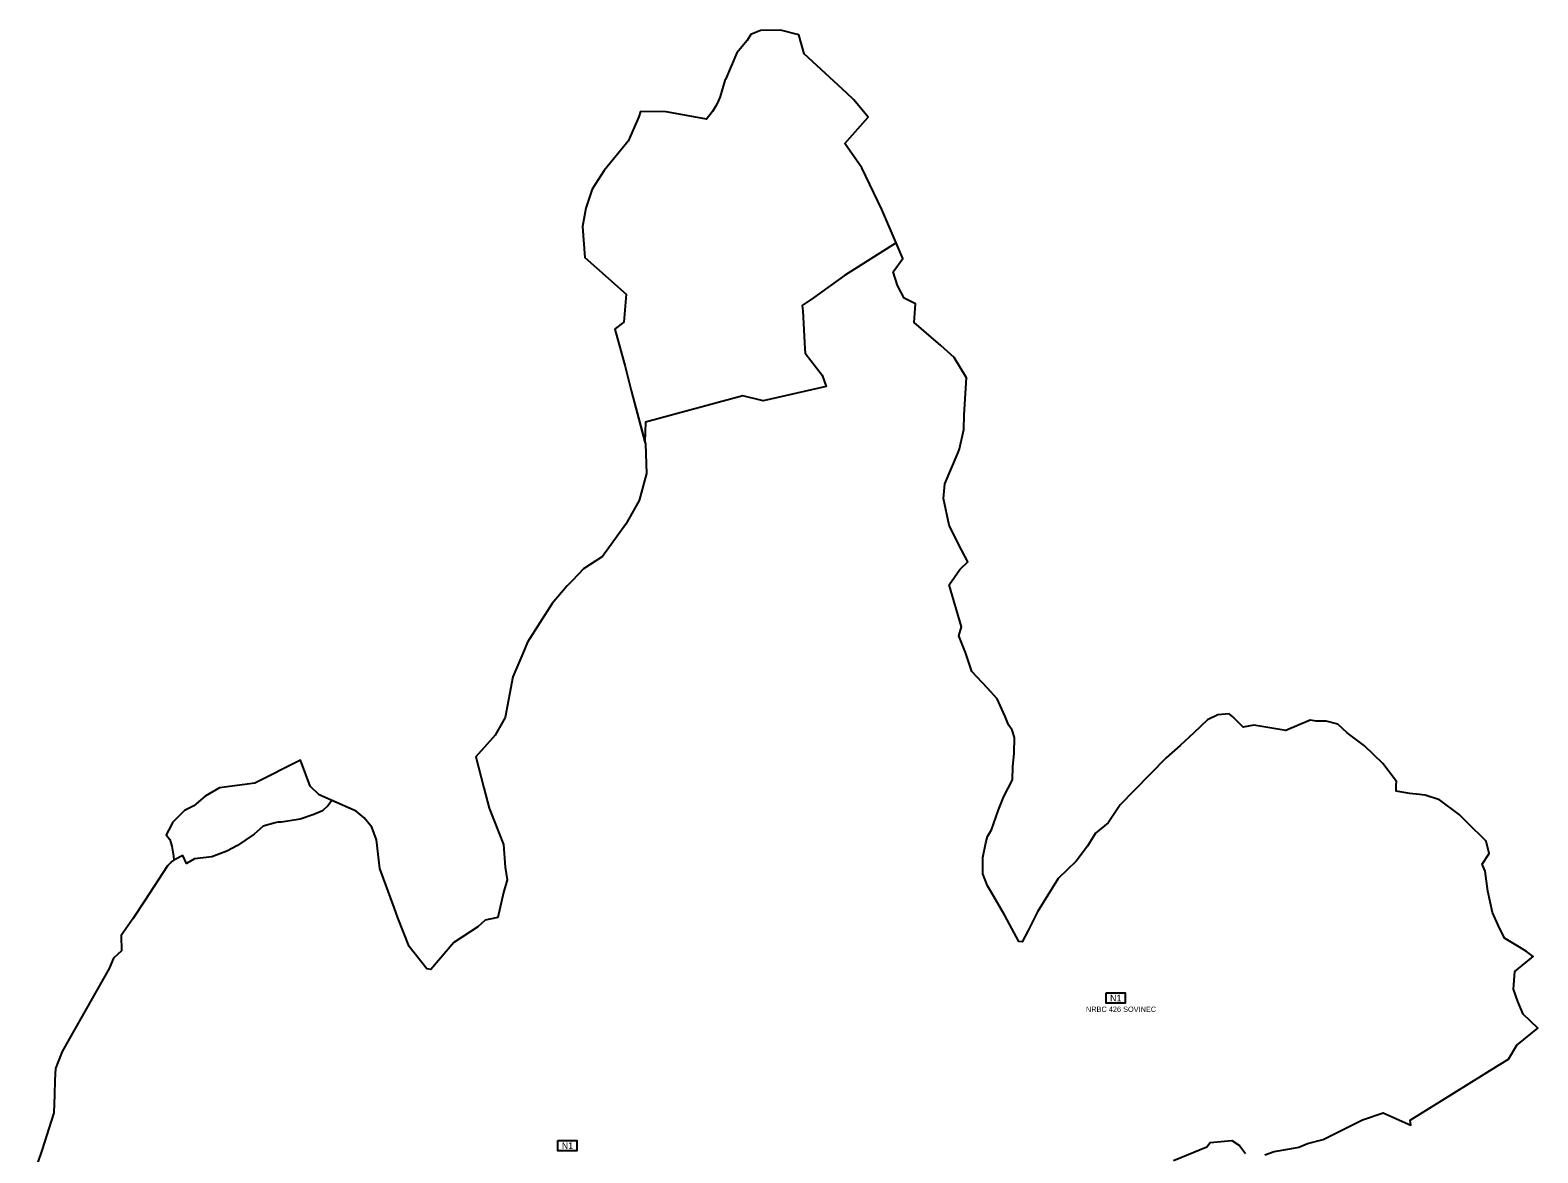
# Model space of a CAD drawing. Extents: x -547623 to -532764, y -1096714 to -1086523.
# Drawn here: x -544615 to -542346, y -1088213 to -1086523 of the extents above; entities that cross this region are included whole.
import ezdxf

# ---------------------------------------------------------------- set-up
doc = ezdxf.new("R2010")
doc.units = 0
for name, color, linetype in [('Vrstva 22', 7, 'Continuous'), ('Vrstva 25', 7, 'Continuous'), ('Vrstva 27', 7, 'Continuous'), ('Vrstva 36', 7, 'Continuous')]:
    doc.layers.add(name, color=color, linetype=linetype)

msp = doc.modelspace()

# ---------------------------------------------------------------- linework, layer by layer
at = {"layer": 'Vrstva 22'}
for points in [[(-542757.3, -1088215.6), (-542743.2, -1088210.9), (-542719.6, -1088206.9), (-542706.2, -1088204.3), (-542692.8, -1088198.9), (-542669.6, -1088192.9), (-542610.2, -1088163.3), (-542579.1, -1088152.4), (-542540.9, -1088169.8), (-542537.3, -1088171.4), (-542538, -1088167.6), (-542538.6, -1088163.8), (-542495.1, -1088136.6), (-542404.8, -1088080.4), (-542390.8, -1088071.8), (-542378.3, -1088050.6), (-542346.4, -1088025.1), (-542368.5, -1088004.3), (-542376.5, -1087984.8), (-542383.2, -1087966.3), (-542381.1, -1087939.9), (-542353.4, -1087917.3), (-542363.4, -1087909.9), (-542374.1, -1087903.1), (-542396.6, -1087889.7), (-542406.3, -1087870.4), (-542414.7, -1087851.1), (-542421.9, -1087819.2), (-542425.9, -1087788.9), (-542430.1, -1087778.4), (-542419.6, -1087762.3), (-542424.1, -1087743.8), (-542452.9, -1087715.7), (-542464.8, -1087703.5), (-542494.4, -1087681.3), (-542516.1, -1087674.6), (-542529, -1087673.1), (-542534.4, -1087672.4), (-542539, -1087671.9), (-542559.7, -1087668.3), (-542559.6, -1087665.6), (-542559.5, -1087659.6), (-542559.3, -1087653.8), (-542579.6, -1087626.6), (-542607.4, -1087600.4), (-542633.1, -1087580.6), (-542647.6, -1087567.8), (-542665.1, -1087563.1), (-542680, -1087563.1), (-542688.8, -1087561.6), (-542725.4, -1087577.2), (-542773.9, -1087569.1), (-542789.6, -1087572.3), (-542805.2, -1087556.6), (-542810.6, -1087551.9), (-542828, -1087553.6), (-542843.4, -1087561.2), (-542863.8, -1087580.8), (-542884.8, -1087599.6), (-542905.4, -1087618.5), (-542953.6, -1087667.4), (-542974.9, -1087689.1), (-542992.8, -1087716.1), (-543011.8, -1087731.9), (-543023.8, -1087751.3), (-543040.9, -1087773.7), (-543067.9, -1087800), (-543099.2, -1087849.9), (-543113.2, -1087878.1), (-543122.2, -1087895.1), (-543127.3, -1087894.8), (-543148.5, -1087855.4), (-543168.6, -1087821.2), (-543174.6, -1087810.8), (-543181.6, -1087793.1), (-543181.6, -1087768.4), (-543177.1, -1087746.2), (-543174.2, -1087736.6), (-543168.6, -1087726.6), (-543157.9, -1087696.8), (-543149.9, -1087676.7), (-543136.8, -1087651.4), (-543136.1, -1087631.8), (-543134.3, -1087611.4), (-543133.6, -1087587.7), (-543137.5, -1087576.6), (-543142.7, -1087568.5), (-543147.8, -1087555.9), (-543159.7, -1087529.3), (-543174.3, -1087513.2), (-543197.8, -1087488.5), (-543207.5, -1087459.9), (-543217.6, -1087434.7), (-543213.4, -1087420.9), (-543232.3, -1087358), (-543216.2, -1087334.6), (-543203.9, -1087323.5), (-543218, -1087296.5), (-543231.9, -1087268), (-543240.6, -1087227.8), (-543238.8, -1087206), (-543218.3, -1087158.6), (-543216.7, -1087153.3), (-543210, -1087124.3), (-543209.7, -1087101.8), (-543206, -1087046.1), (-543224.8, -1087015.9), (-543244.7, -1086997.7), (-543284.8, -1086963), (-543282.9, -1086935.1), (-543299.7, -1086926.5), (-543309.7, -1086907.4), (-543316.1, -1086886.8), (-543301.9, -1086866.5), (-543333.5, -1086792.8), (-543363.4, -1086730.3), (-543389.2, -1086693.5), (-543353.8, -1086654), (-543375.4, -1086627.8), (-543386.3, -1086617.4), (-543450.1, -1086558.6), (-543458.3, -1086530.2), (-543486, -1086523), (-543516.1, -1086523.6), (-543530.3, -1086529.6), (-543536.2, -1086538.5), (-543551.3, -1086557.2), (-543568.4, -1086597.4), (-543569.8, -1086599), (-543576.4, -1086623), (-543580.1, -1086631.5), (-543583.5, -1086638.1), (-543588.3, -1086645.6), (-543597.2, -1086656.9), (-543599.9, -1086656.6), (-543658, -1086646.1), (-543696.5, -1086645.6), (-543698.9, -1086653.3), (-543715.1, -1086689.9), (-543751.3, -1086734.4), (-543769.4, -1086762.4), (-543778.8, -1086790.9), (-543783.9, -1086818.7), (-543780.3, -1086865), (-543762.7, -1086880.6), (-543717.9, -1086920.4), (-543721.7, -1086962.4), (-543734, -1086972.1), (-543735.1, -1086973), (-543719.4, -1087029), (-543710.3, -1087065.5), (-543689, -1087145.7), (-543687.6, -1087190.3), (-543698.3, -1087231), (-543718.5, -1087266.7), (-543753.7, -1087315.3), (-543782.1, -1087333.9), (-543798.9, -1087351.4), (-543806.7, -1087359.6), (-543829.2, -1087386.1), (-543866.7, -1087444.2), (-543873.6, -1087461.1), (-543888.3, -1087496.6), (-543900, -1087557.7), (-543915.2, -1087584), (-543944.4, -1087616.9), (-543932.1, -1087663.6), (-543924.3, -1087694), (-543902.6, -1087748.9), (-543900.1, -1087783), (-543897.2, -1087801.7), (-543902.6, -1087821.2), (-543910.9, -1087858.5), (-543913.5, -1087859.1), (-543930.1, -1087862.6), (-543941.4, -1087872.8), (-543977.2, -1087896.4), (-544011.8, -1087937), (-544017.7, -1087936), (-544044.6, -1087902.4), (-544061.6, -1087859.3), (-544067.2, -1087843.8), (-544088.6, -1087784.8), (-544093.4, -1087741.8), (-544100.8, -1087722.7), (-544112, -1087708.5), (-544124.1, -1087698.5), (-544179.8, -1087673.9), (-544193.2, -1087660.7), (-544208.2, -1087622), (-544276.9, -1087656.4), (-544329.8, -1087663.6), (-544351.3, -1087676), (-544368.6, -1087690.3), (-544382.3, -1087697.4), (-544400.6, -1087715.7), (-544402.3, -1087719), (-544410, -1087734.1), (-544404.6, -1087741.2), (-544401.5, -1087751.2), (-544399, -1087766.4), (-544398.5, -1087772.5), (-544401.4, -1087774.4), (-544408, -1087780.6), (-544442.9, -1087834), (-544460.4, -1087860.8), (-544478, -1087885.6), (-544477.3, -1087908.6), (-544489.2, -1087919.8), (-544495.9, -1087935.5), (-544549, -1088029.3), (-544566.3, -1088060.3), (-544576.5, -1088086.1), (-544577.7, -1088103.5), (-544578.3, -1088125.3), (-544579, -1088152.5), (-544597.1, -1088209.1), (-544614.7, -1088260.3)], [(-542894.4, -1088224.2), (-542844.6, -1088203.7), (-542839.3, -1088197.4), (-542806.8, -1088194.4), (-542795.1, -1088201.7), (-542786.1, -1088213.7)]]:
    msp.add_lwpolyline(points, dxfattribs=at)
at = {"layer": 'Vrstva 25'}
for points in [[(-543312, -1086842.9), (-543389.5, -1086892.5), (-543436.2, -1086926.1), (-543453.2, -1086937.2), (-543452.3, -1086945.3), (-543449.2, -1087002.6), (-543448.8, -1087009.2), (-543423.4, -1087042.3), (-543417.1, -1087059.5), (-543511.7, -1087080.7), (-543542.4, -1087073.3), (-543689.1, -1087113), (-543689.8, -1087142.9), (-543689, -1087145.7), (-543688.9, -1087150.3)], [(-544158.1, -1087683.5), (-544160.8, -1087682.3), (-544166.5, -1087689.8), (-544174.7, -1087698.3), (-544187.9, -1087703.8), (-544208.4, -1087710.5), (-544236.6, -1087714.9), (-544242.1, -1087714.9), (-544246, -1087716), (-544264.2, -1087721), (-544277.5, -1087733.1), (-544302.9, -1087750.3), (-544319, -1087758.6), (-544341.6, -1087767.4), (-544367.6, -1087770.2), (-544379.7, -1087777.2), (-544384.9, -1087765.1), (-544398.5, -1087772.5), (-544401.4, -1087774.4), (-544403.2, -1087776.1)]]:
    msp.add_lwpolyline(points, dxfattribs=at)
at = {"layer": 'Vrstva 27'}
for points in [[(-543312, -1086842.9), (-543333.5, -1086792.8), (-543363.4, -1086730.3), (-543389.2, -1086693.5), (-543353.8, -1086654), (-543375.4, -1086627.8), (-543386.3, -1086617.4), (-543450.1, -1086558.6), (-543458.3, -1086530.2), (-543486, -1086523), (-543516.1, -1086523.6), (-543530.3, -1086529.6), (-543536.2, -1086538.5), (-543551.3, -1086557.2), (-543568.4, -1086597.4), (-543569.8, -1086599), (-543576.4, -1086623), (-543580.1, -1086631.5), (-543583.5, -1086638.1), (-543588.3, -1086645.6), (-543597.2, -1086656.9), (-543599.9, -1086656.6), (-543658, -1086646.1), (-543696.5, -1086645.6), (-543698.9, -1086653.3), (-543715.1, -1086689.9), (-543751.3, -1086734.4), (-543769.4, -1086762.4), (-543778.8, -1086790.9), (-543783.9, -1086818.7), (-543780.3, -1086865), (-543762.7, -1086880.6), (-543717.9, -1086920.4), (-543721.7, -1086962.4), (-543734, -1086972.1), (-543735.1, -1086973), (-543719.4, -1087029), (-543710.3, -1087065.5), (-543689.8, -1087142.9)], [(-542757.3, -1088215.6), (-542743.2, -1088210.9), (-542719.6, -1088206.9), (-542706.2, -1088204.3), (-542692.8, -1088198.9), (-542669.6, -1088192.9), (-542610.2, -1088163.3), (-542579.1, -1088152.4), (-542540.9, -1088169.8), (-542537.3, -1088171.4), (-542538, -1088167.6), (-542538.6, -1088163.8), (-542495.1, -1088136.6), (-542404.8, -1088080.4), (-542390.8, -1088071.8), (-542378.3, -1088050.6), (-542346.4, -1088025.1), (-542368.5, -1088004.3), (-542376.5, -1087984.8), (-542383.2, -1087966.3), (-542381.1, -1087939.9), (-542353.4, -1087917.3), (-542363.4, -1087909.9), (-542374.1, -1087903.1), (-542396.6, -1087889.7), (-542406.3, -1087870.4), (-542414.7, -1087851.1), (-542421.9, -1087819.2), (-542425.9, -1087788.9), (-542430.1, -1087778.4), (-542419.6, -1087762.3), (-542424.1, -1087743.8), (-542452.9, -1087715.7), (-542464.8, -1087703.5), (-542494.4, -1087681.3), (-542516.1, -1087674.6), (-542529, -1087673.1), (-542534.4, -1087672.4), (-542539, -1087671.9), (-542559.7, -1087668.3), (-542559.6, -1087665.6), (-542559.5, -1087659.6), (-542559.3, -1087653.8), (-542579.6, -1087626.6), (-542607.4, -1087600.4), (-542633.1, -1087580.6), (-542647.6, -1087567.8), (-542665.1, -1087563.1), (-542680, -1087563.1), (-542688.8, -1087561.6), (-542725.4, -1087577.2), (-542773.9, -1087569.1), (-542789.6, -1087572.3), (-542805.2, -1087556.6), (-542810.6, -1087551.9), (-542828, -1087553.6), (-542843.4, -1087561.2), (-542863.8, -1087580.8), (-542884.8, -1087599.6), (-542905.4, -1087618.5), (-542953.6, -1087667.4), (-542974.9, -1087689.1), (-542992.8, -1087716.1), (-543011.8, -1087731.9), (-543023.8, -1087751.3), (-543040.9, -1087773.7), (-543067.9, -1087800), (-543099.2, -1087849.9), (-543113.2, -1087878.1), (-543122.2, -1087895.1), (-543127.3, -1087894.8), (-543148.5, -1087855.4), (-543168.6, -1087821.2), (-543174.6, -1087810.8), (-543181.6, -1087793.1), (-543181.6, -1087768.4), (-543177.1, -1087746.2), (-543174.2, -1087736.6), (-543168.6, -1087726.6), (-543157.9, -1087696.8), (-543149.9, -1087676.7), (-543136.8, -1087651.4), (-543136.1, -1087631.8), (-543134.3, -1087611.4), (-543133.6, -1087587.7), (-543137.5, -1087576.6), (-543142.7, -1087568.5), (-543147.8, -1087555.9), (-543159.7, -1087529.3), (-543174.3, -1087513.2), (-543197.8, -1087488.5), (-543207.5, -1087459.9), (-543217.6, -1087434.7), (-543213.4, -1087420.9), (-543232.3, -1087358), (-543216.2, -1087334.6), (-543203.9, -1087323.5), (-543218, -1087296.5), (-543231.9, -1087268), (-543240.6, -1087227.8), (-543238.8, -1087206), (-543218.3, -1087158.6), (-543216.7, -1087153.3), (-543210, -1087124.3), (-543209.7, -1087101.8), (-543206, -1087046.1), (-543224.8, -1087015.9), (-543244.7, -1086997.7), (-543284.8, -1086963), (-543282.9, -1086935.1), (-543299.7, -1086926.5), (-543309.7, -1086907.4), (-543316.1, -1086886.8), (-543301.9, -1086866.5), (-543312, -1086842.9)], [(-543689.8, -1087142.9), (-543689, -1087145.7), (-543687.6, -1087190.3), (-543698.3, -1087231), (-543718.5, -1087266.7), (-543753.7, -1087315.3), (-543782.1, -1087333.9), (-543798.9, -1087351.4), (-543806.7, -1087359.6), (-543829.2, -1087386.1), (-543866.7, -1087444.2), (-543873.6, -1087461.1), (-543888.3, -1087496.6), (-543900, -1087557.7), (-543915.2, -1087584), (-543944.4, -1087616.9), (-543932.1, -1087663.6), (-543924.3, -1087694), (-543902.6, -1087748.9), (-543900.1, -1087783), (-543897.2, -1087801.7), (-543902.6, -1087821.2), (-543910.9, -1087858.5), (-543913.5, -1087859.1), (-543930.1, -1087862.6), (-543941.4, -1087872.8), (-543977.2, -1087896.4), (-544011.8, -1087937), (-544017.7, -1087936), (-544044.6, -1087902.4), (-544061.6, -1087859.3), (-544067.2, -1087843.8), (-544088.6, -1087784.8), (-544093.4, -1087741.8), (-544100.8, -1087722.7), (-544112, -1087708.5), (-544124.1, -1087698.5), (-544160.8, -1087682.3)], [(-544160.8, -1087682.3), (-544179.8, -1087673.9), (-544193.2, -1087660.7), (-544208.2, -1087622), (-544276.9, -1087656.4), (-544329.8, -1087663.6), (-544351.3, -1087676), (-544368.6, -1087690.3), (-544382.3, -1087697.4), (-544400.6, -1087715.7), (-544402.3, -1087719), (-544410, -1087734.1), (-544404.6, -1087741.2), (-544401.5, -1087751.2), (-544399, -1087766.4), (-544398.5, -1087772.5)], [(-544398.5, -1087772.5), (-544401.4, -1087774.4), (-544408, -1087780.6), (-544442.9, -1087834), (-544460.4, -1087860.8), (-544478, -1087885.6), (-544477.3, -1087908.6), (-544489.2, -1087919.8), (-544495.9, -1087935.5), (-544549, -1088029.3), (-544566.3, -1088060.3), (-544576.5, -1088086.1), (-544577.7, -1088103.5), (-544578.3, -1088125.3), (-544579, -1088152.5), (-544597.1, -1088209.1), (-544614.7, -1088260.3)], [(-542894.4, -1088224.2), (-542844.6, -1088203.7), (-542839.3, -1088197.4), (-542806.8, -1088194.4), (-542795.1, -1088201.7), (-542786.1, -1088213.7)]]:
    msp.add_lwpolyline(points, dxfattribs=at)
at = {"layer": 'Vrstva 36'}
for points in [[(-542995.9, -1087972.1), (-542967.3, -1087972.1), (-542967.3, -1087987.6), (-542995.9, -1087987.6)], [(-543820.8, -1088194.3), (-543792.2, -1088194.3), (-543792.2, -1088209.8), (-543820.8, -1088209.8)]]:
    msp.add_lwpolyline(points, close=True, dxfattribs=at)

# ---------------------------------------------------------------- texts
for s, height, p in [('N1', 10, (-542990, -1087984.9)), ('NRBC 426 SOVINEC', 8, (-543026.3, -1088000.7)), ('N1', 10, (-543814.9, -1088207))]:
    msp.add_text(s, height=height, dxfattribs=at).set_placement(p)

doc.saveas('drawing.dxf')
